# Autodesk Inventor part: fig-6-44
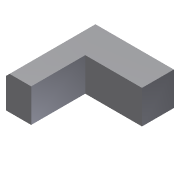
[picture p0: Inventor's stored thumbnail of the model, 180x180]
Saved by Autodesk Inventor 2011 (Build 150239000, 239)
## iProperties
Created: 2010-08
Part Number: fig-6-44
Document SubType Name: Modeling
Designer: CADSoft
Density: 1 g/cm^3
Author: CADSoft
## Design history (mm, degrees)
sketch "Sketch1"
  geometry: L1 (-33.983, 0)-(-48.97, 0); L2 (-48.97, 0)-(-48.97, 51.503); L3 (-48.97, 51.503)-(0, 51.503); L4 (0, 51.503)-(0, 32.411); L5 (-33.983, 0)-(-33.983, 32.411); L6 (-33.983, 32.411)-(0, 32.411); 1 further point
  constraints: 12 end point, 3 parallel, 2 perpendicular, 1 horizontal
extrude "Extrusion1" new body sketch "Sketch1" distance "d0" = 20; taper "d1" = 0 deg
chamfer "Chamfer1" distance "d2" = 2; stored, may be unused: second distance "d3" = 2, angle "d4" = 45 deg
body "Solid1"
